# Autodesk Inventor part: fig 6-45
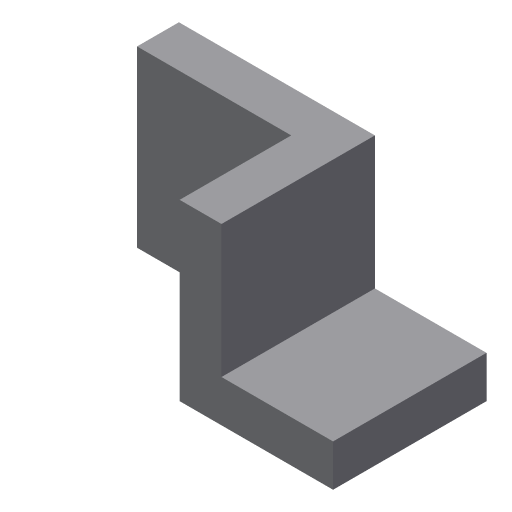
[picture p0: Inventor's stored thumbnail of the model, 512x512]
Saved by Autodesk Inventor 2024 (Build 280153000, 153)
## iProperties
Shininess: 77.0
Angle Display Precision: 2
Document Length Units: 11269
Document Angle Units: 11279
Document Time Units: 11290
Document Mass Units: 11283
Document Length Units Precision: 3
Document Angle Units Precision: 2
Created: 2001-12
Part Number: fig 6-45
Document SubType Name: Modeling
Designer: Renu Muthoo
Density: 1 g/cm^3
Material: Generic
Appearance: Default
Density: 0.0
Volumn: 0.0
Area: 0.0
PropertySet Name: Model Information
Control State: 0
Master: False
Checked Out: False
Author: Renu Muthoo
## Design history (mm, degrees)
sketch "Sketch2"
  geometry: L1 (16.794, 27.142)-(16.794, -22.858); L2 (16.794, -22.858)-(-27.206, -22.858); L3 (-27.206, -22.858)-(-27.206, -10.858); L4 (-27.206, -10.858)-(4.794, -10.858); L5 (4.794, -10.858)-(4.794, 27.142); L6 (4.794, 27.142)-(16.794, 27.142)
  constraints: 12 end point, 4 parallel, 2 perpendicular, 1 vertical
  dimensions: "d0" = 44 distance of L1.end L2.end; "d1" = 50 distance of L1.start L1.end; "d2" = 12 distance of L2.end L3.end
extrude "Extrusion1" new body sketch "Sketch2" distance "d3" = 44; taper "d4" = 0 deg
sketch "Sketch4"
  geometry: L1 (-16.794, -27.142)-(-16.794, 22.858) reference; L2 (27.206, 22.858)-(27.206, 10.858) reference; L3 (-16.794, -27.142)-(-61.001, -27.142); L4 (-61.001, -27.142)-(-61.001, 22.858); L5 (-61.001, 22.858)-(-16.794, 22.858)
  constraints: 6 end point, 2 perpendicular, 1 parallel
extrude "Extrusion3" join sketch "Sketch4" distance "d13" = 12; taper "d14" = 0 deg
body "Solid1"
node "Sketch1"
